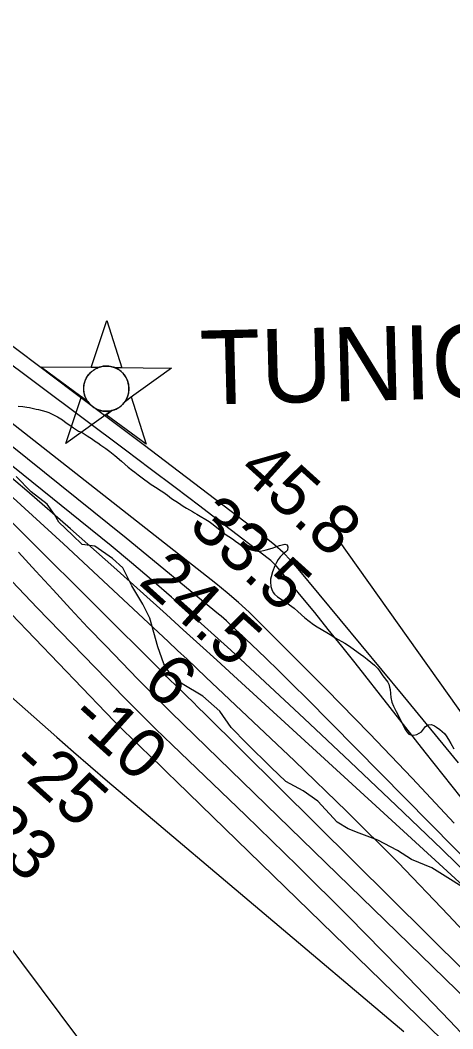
# Model space of a CAD drawing. Extents: x 3192986 to 3230865, y 867483 to 892886.
# Drawn here: x 3217089 to 3217672, y 877193 to 878555 of the extents above; entities that cross this region are included whole.
import ezdxf

# ---------------------------------------------------------------- set-up
doc = ezdxf.new("R2010")
doc.units = 0
for name, color, linetype in [('V-CHAN-NAID', 7, 'Continuous'), ('V-RIVR-EDGE', 7, 'Continuous'), ('V-RIVR-RANG', 7, 'Continuous'), ('V-SITE-VEGE', 7, 'Continuous'), ('V-TOPO-DPTH', 7, 'Continuous'), ('V-TOPO-MAJR', 7, 'Continuous'), ('V-TOPO-MINR', 7, 'Continuous'), ('V-TOPO-WATR', 7, 'Continuous')]:
    doc.layers.add(name, color=color, linetype=linetype)

msp = doc.modelspace()

# ---------------------------------------------------------------- linework, layer by layer
at = {"layer": 'V-CHAN-NAID'}
for points in [[(3217194, 878085.7), (3217184.4, 878085.8), (3217205.5, 878149.3), (3217225.8, 878085.5), (3217216.2, 878085.6), (3217214.6, 878086.1), (3217212.5, 878086.7), (3217210.5, 878087.2), (3217208.4, 878087.5), (3217207.3, 878087.6), (3217205.7, 878087.7), (3217204, 878087.7), (3217202.6, 878087.6), (3217200.7, 878087.4), (3217199.4, 878087.2), (3217197.6, 878086.8), (3217196.1, 878086.4), (3217195, 878086.1)], [(3217194, 878085.7), (3217117.5, 878086.2), (3217179.1, 878040.9), (3217178, 878042.8), (3217177.2, 878044.4), (3217176.3, 878046.4), (3217175.6, 878048.4), (3217175.3, 878049.7), (3217174.9, 878051.4), (3217174.7, 878052.8), (3217174.5, 878054.4), (3217174.4, 878056.1), (3217174.4, 878057.7), (3217174.5, 878059.8), (3217174.6, 878061.4), (3217175, 878063.6), (3217175.5, 878065.5), (3217176.1, 878067.4), (3217176.8, 878069.1), (3217177.5, 878070.7), (3217178.3, 878072.2), (3217179.4, 878074), (3217180.4, 878075.4), (3217181.4, 878076.7), (3217182.4, 878077.8), (3217183.7, 878079.2), (3217184.8, 878080.2), (3217186.5, 878081.5), (3217187.7, 878082.4), (3217189.4, 878083.5), (3217191.1, 878084.4), (3217192.6, 878085.1)], [(3217216.2, 878085.6), (3217292.7, 878085), (3217230.5, 878040.5), (3217231.4, 878042), (3217232.4, 878043.8), (3217233.1, 878045.4), (3217233.8, 878047.4), (3217234.4, 878049.1), (3217234.8, 878050.8), (3217235.1, 878052.8), (3217235.3, 878054.4), (3217235.4, 878056.6), (3217235.4, 878058.6), (3217235.2, 878060.9), (3217234.9, 878062.6), (3217234.5, 878064.8), (3217233.8, 878067), (3217233.1, 878069), (3217232.4, 878070.4), (3217231.4, 878072.3), (3217230.3, 878074.1), (3217229.1, 878075.8), (3217227.9, 878077.3), (3217226.6, 878078.7), (3217225, 878080.2), (3217223.2, 878081.6), (3217221.5, 878082.8), (3217219.7, 878083.9), (3217218.2, 878084.7)], [(3217212.4, 878027.6), (3217150.2, 877983.1), (3217171.4, 878046.5), (3217179.1, 878040.9), (3217179.7, 878039.9), (3217181.1, 878038), (3217182.3, 878036.6), (3217183.8, 878035.1), (3217185.2, 878033.9), (3217186.6, 878032.7), (3217188, 878031.7), (3217189.7, 878030.7), (3217191.4, 878029.8), (3217193.2, 878029), (3217194.7, 878028.4), (3217196.3, 878027.9), (3217198.5, 878027.3), (3217200, 878027), (3217202.1, 878026.8), (3217203.6, 878026.7), (3217205.5, 878026.6), (3217207.2, 878026.7), (3217208.9, 878026.9), (3217210.8, 878027.2)], [(3217230.5, 878040.5), (3217238.3, 878046.1), (3217258.5, 877982.3), (3217204.6, 878022), (3217212.4, 878027.6), (3217214.1, 878028.1), (3217215.7, 878028.6), (3217217.9, 878029.5), (3217219.6, 878030.4), (3217221.5, 878031.5), (3217223.2, 878032.7), (3217224.8, 878034), (3217226.1, 878035.2), (3217227.4, 878036.6), (3217228.6, 878038), (3217229.8, 878039.4)]]:
    msp.add_lwpolyline(points, close=True, dxfattribs=at)
msp.add_circle((3217204.9, 878057.2), 30.5, dxfattribs=at)
at = {"layer": 'V-RIVR-EDGE'}
msp.add_lwpolyline([(3217706.5, 877370.9), (3217644, 877410.2), (3217616.6, 877421.6), (3217597.5, 877433.8), (3217571.1, 877447.4), (3217545.9, 877457), (3217531.1, 877462.7), (3217516.3, 877471.8), (3217490.3, 877500.1), (3217470.4, 877514.1), (3217446.9, 877526.8), (3217427.4, 877545.9), (3217394.5, 877578.2), (3217373.2, 877599.5), (3217358.1, 877621.8), (3217335.1, 877641.8), (3217307.3, 877658.8), (3217293, 877669.3), (3217282.6, 877685.8), (3217274.4, 877708.5), (3217263.6, 877747.2), (3217254.1, 877766.3), (3217239.4, 877791.1), (3217227.3, 877815.5), (3217213.4, 877828.1), (3217189.5, 877844.7), (3217172.1, 877846.9), (3217159.1, 877859.6), (3217140.9, 877877), (3217134.9, 877887.5), (3217124.9, 877901.4), (3217103.6, 877918), (3217083.3, 877938.4)], dxfattribs=at)
at = {"layer": 'V-SITE-VEGE'}
for points in [[(3217086, 878033.7), (3217092.4, 878033.3), (3217097.6, 878032.3), (3217101.4, 878031.7), (3217110.3, 878029.7), (3217113.5, 878029.1), (3217118.1, 878027.9), (3217123.2, 878026.3), (3217127.2, 878024.9), (3217139, 878019.3), (3217145.5, 878015.2), (3217150.7, 878011.2), (3217157.1, 878007), (3217160.4, 878004.2), (3217167.4, 878000), (3217170.4, 877999), (3217173.4, 877997), (3217178.9, 877993.7), (3217186.1, 877988.9), (3217189.1, 877986.7), (3217193.3, 877984.1), (3217197.6, 877981.1), (3217204, 877976.6), (3217209.6, 877972.4), (3217216.3, 877967), (3217225.1, 877959.4), (3217234.2, 877951.3), (3217240, 877946.7), (3217243.2, 877944.5), (3217248, 877940.9), (3217251.2, 877938.1), (3217265.5, 877928), (3217273.4, 877923), (3217276.4, 877920.8), (3217281, 877917.8), (3217287.4, 877913.5), (3217292.9, 877909.1), (3217302.1, 877902.9), (3217308.6, 877898.5), (3217313, 877895.8), (3217321, 877891.4), (3217323.7, 877889.7), (3217327.1, 877887.9), (3217343.5, 877877.8), (3217349, 877874), (3217365.3, 877860.8), (3217375, 877854.3), (3217379.2, 877851.2), (3217388, 877845.2), (3217392.4, 877842.8), (3217398.6, 877839.9), (3217405.7, 877838.4), (3217409.4, 877837.8), (3217412.8, 877837.7), (3217416.9, 877838.5), (3217420.6, 877839.7), (3217428.5, 877841.8), (3217438.6, 877845.3), (3217445.6, 877847.4), (3217448.8, 877846.5), (3217449.8, 877843.6), (3217449.5, 877839.3), (3217447, 877836.8), (3217443.1, 877833.6), (3217439.6, 877830.2), (3217436.9, 877826.7), (3217434.4, 877822.6), (3217432, 877818), (3217428.9, 877809.7), (3217427.2, 877803.2), (3217426.4, 877799.8), (3217426.4, 877796.3), (3217426.9, 877790.3), (3217428, 877786), (3217429.8, 877782.2), (3217431.7, 877779.8), (3217435.7, 877776), (3217448.8, 877767.6), (3217458.5, 877760.8), (3217463.3, 877756.3), (3217472.8, 877747.9), (3217484.3, 877738.9), (3217489.5, 877735.5), (3217502.3, 877728.2), (3217509.3, 877723.9), (3217513.7, 877721), (3217526.6, 877713.5), (3217531.4, 877710.6), (3217534.9, 877708.3), (3217548, 877698.9), (3217552.2, 877695.5), (3217557, 877692)], [(3217557, 877692), (3217566.7, 877683.8), (3217570.8, 877679.6), (3217573.6, 877676.4), (3217578.1, 877669.5), (3217584.5, 877661), (3217585.8, 877658.2), (3217587.1, 877654.2), (3217587.8, 877650.9), (3217588.9, 877640.1), (3217590.2, 877634.1), (3217592.3, 877628.6), (3217595.8, 877621.3), (3217599, 877615.4), (3217602.2, 877608.7), (3217608.4, 877596.7), (3217610.1, 877593.8), (3217613.1, 877590.8), (3217615.9, 877589.8), (3217619.9, 877589.4), (3217623.8, 877590.3), (3217627, 877592), (3217630, 877593.9), (3217635.6, 877600.9), (3217639.2, 877603.5), (3217643.6, 877603.6), (3217647.5, 877602), (3217650.5, 877600.1), (3217654.8, 877597), (3217660.9, 877591.4), (3217663.2, 877588.5), (3217666.5, 877583.5), (3217669.6, 877578.3), (3217673.7, 877570.8)]]:
    msp.add_lwpolyline(points, dxfattribs=at)
at = {"layer": 'V-TOPO-DPTH'}
for points in [[(3217718.5, 877375.6), (3217657.3, 877435.3), (3217595.8, 877494.6), (3217533.9, 877553.4), (3217471.6, 877611.9), (3217398.9, 877679.6), (3217372.7, 877703.9), (3217346.3, 877727.9), (3217319.7, 877751.8), (3217292.9, 877775.5), (3217265.9, 877798.9), (3217238.8, 877822), (3217211.3, 877844.9), (3217183.6, 877867.5), (3216649.7, 878298.1), (3216627.4, 878315.8), (3216604.9, 878333.2), (3216582, 878350.2), (3216558.9, 878366.9), (3216314.9, 878540.4), (3216245.5, 878588.9)], [(3216228.1, 878571.6), (3216302.6, 878523.2), (3216376.3, 878473.6), (3216449.3, 878423), (3216562, 878343.6), (3216578.1, 878331.9), (3216594.1, 878320.1), (3216609.7, 878307.8), (3216625.2, 878295.4), (3216804.5, 878147.9), (3216891.8, 878074.6), (3216978.2, 878000.3), (3217063.2, 877924.4), (3217147.2, 877847.5), (3217288.3, 877715.8), (3217301.1, 877703.8), (3217313.8, 877691.8), (3217326.6, 877679.8), (3217339.3, 877667.8), (3217458.7, 877554.6), (3217529.2, 877486.4), (3217598.6, 877417.2), (3217666.5, 877346.5), (3217733.3, 877274.7)], [(3216228.1, 878571.6), (3216302.6, 878523.2), (3216376.3, 878473.6), (3216449.3, 878423), (3216562, 878343.6), (3216578.1, 878331.9), (3216594.1, 878320.1), (3216609.7, 878307.8), (3216625.2, 878295.4), (3216804.5, 878147.9), (3216891.8, 878074.6), (3216978.2, 878000.3), (3217063.2, 877924.4), (3217147.2, 877847.5), (3217288.3, 877715.8), (3217301.1, 877703.8), (3217313.8, 877691.8), (3217326.6, 877679.8), (3217339.3, 877667.8), (3217458.7, 877554.6), (3217529.2, 877486.4), (3217598.6, 877417.2), (3217666.5, 877346.5), (3217733.3, 877274.7)], [(3217086.3, 877836.5), (3217109.6, 877811), (3217132.9, 877785.4), (3217156.4, 877760), (3217180.1, 877734.9), (3217204.1, 877709.9), (3217247.5, 877665.1), (3217258.5, 877653.8), (3217269.6, 877642.6), (3217280.7, 877631.5), (3217292, 877620.5), (3217709.7, 877214)], [(3217709.7, 877214), (3217292, 877620.5), (3217280.7, 877631.5), (3217269.6, 877642.6), (3217258.5, 877653.8), (3217247.5, 877665.1), (3217204.1, 877709.9), (3217180.1, 877734.9), (3217156.4, 877760), (3217132.9, 877785.4), (3217109.6, 877811), (3217086.3, 877836.5)], [(3217771.9, 877067.3), (3217299.6, 877527), (3217287.6, 877538.6), (3217275.7, 877550.1), (3217263.7, 877561.6), (3217251.6, 877573), (3217239.6, 877584.5), (3217227.7, 877596.1), (3217216, 877607.9), (3217204.4, 877619.8), (3217012.3, 877819.9)], [(3217771.9, 877067.3), (3217299.6, 877527), (3217287.6, 877538.6), (3217275.7, 877550.1), (3217263.7, 877561.6), (3217251.6, 877573), (3217239.6, 877584.5), (3217227.7, 877596.1), (3217216, 877607.9), (3217204.4, 877619.8), (3217012.3, 877819.9)], [(3216912.6, 877785.8), (3217137.9, 877586.6), (3217160.6, 877566.7), (3217183.4, 877546.9), (3217206.3, 877527.2), (3217229.3, 877507.7), (3217606.1, 877189.4)], [(3216912.6, 877785.8), (3217137.9, 877586.6), (3217160.6, 877566.7), (3217183.4, 877546.9), (3217206.3, 877527.2), (3217229.3, 877507.7), (3217606.1, 877189.4)], [(3217167.7, 877179.3), (3217040.1, 877350)], [(3217167.7, 877179.3), (3217040.1, 877350)]]:
    msp.add_lwpolyline(points, dxfattribs=at)
at = {"layer": 'V-TOPO-MAJR'}
msp.add_lwpolyline([(3217683.7, 877505), (3217635, 877566.6), (3217540.4, 877686.9), (3217522.4, 877709.6), (3217504.3, 877732.2), (3217486, 877754.8), (3217467.7, 877777.2), (3217437.3, 877814.3), (3217434, 877818), (3217430.5, 877821.6), (3217426.8, 877825), (3217423, 877828.1), (3217364.4, 877873), (3217331, 877898.4), (3217297.7, 877923.7), (3217264.2, 877949), (3217230.7, 877974.1), (3216705.5, 878366.9), (3216683.2, 878384.2), (3216661.2, 878402), (3216639.9, 878420.5), (3216619, 878439.5), (3216440, 878607.1)], dxfattribs=at)
at = {"layer": 'V-TOPO-MINR'}
for points in [[(3217674.3, 877470.5), (3217617.5, 877531.5), (3217559.7, 877591.7), (3217501.4, 877651.3), (3217411.7, 877741.6), (3217397.5, 877755.3), (3217383, 877768.7), (3217368, 877781.6), (3217352.7, 877794.1), (3216777, 878246.3), (3216752.2, 878265.5), (3216727.1, 878284.5), (3216701.9, 878303.2), (3216676.4, 878321.6), (3216650.8, 878339.8), (3216625.1, 878357.9), (3216599.3, 878375.9), (3216573.4, 878393.7), (3216102.7, 878717.2)], [(3217907.9, 877200.2), (3217474.8, 877639.1), (3217456.6, 877657.4), (3217438.2, 877675.6), (3217419.7, 877693.6), (3217401, 877711.5), (3217370.2, 877740.7), (3217366.8, 877743.9), (3217363.4, 877747), (3217359.9, 877750), (3217356.4, 877752.9), (3217231.4, 877855.2), (3217165.2, 877909.1), (3217098.7, 877962.5), (3217031.8, 878015.5), (3216964.6, 878068.1), (3216665.3, 878300.6), (3216638.6, 878321.2), (3216611.6, 878341.4), (3216584.4, 878361.4), (3216557, 878381.1), (3216210.8, 878626.6)], [(3217718.5, 877375.6), (3217657.3, 877435.3), (3217595.8, 877494.6), (3217533.9, 877553.4), (3217471.6, 877611.9), (3217398.9, 877679.6), (3217372.7, 877703.9), (3217346.3, 877727.9), (3217319.7, 877751.8), (3217292.9, 877775.5), (3217265.9, 877798.9), (3217238.8, 877822), (3217211.3, 877844.9), (3217183.6, 877867.5), (3216649.7, 878298.1), (3216627.4, 878315.8), (3216604.9, 878333.2), (3216582, 878350.2), (3216558.9, 878366.9), (3216314.9, 878540.4), (3216245.5, 878588.9)], [(3217824.6, 877258.9), (3217376.3, 877670), (3217353.8, 877690.6), (3217331.2, 877711.2), (3217308.6, 877731.7), (3217285.9, 877752.1), (3217215, 877816), (3217156.5, 877867.9), (3217097.4, 877919.2), (3217037.7, 877969.6), (3216977.4, 878019.5), (3216637.5, 878296.7), (3216618.6, 878311.8), (3216599.4, 878326.6), (3216580, 878341.1), (3216560.4, 878355.3), (3216415.4, 878458), (3216328, 878518.7), (3216240, 878578.5)], [(3217679.9, 877552.1), (3217642.7, 877597.6), (3217605.4, 877643), (3217463.9, 877813.8), (3217453.9, 877825.1), (3217443.3, 877835.9), (3217432.1, 877845.9), (3217420.3, 877855.5), (3217254.4, 877981.6), (3217159.2, 878053.6), (3217063.9, 878125.4), (3216968.3, 878197), (3216872.5, 878268.3), (3216702.2, 878394.7), (3216687.8, 878405.8), (3216673.7, 878417.2), (3216659.9, 878429.1), (3216646.4, 878441.3), (3216536.9, 878543.8), (3216511.9, 878568.6)], [(3217840.3, 877119.9), (3217337.1, 877618.6), (3217329.3, 877626.4), (3217321.4, 877634.2), (3217313.5, 877641.9), (3217305.6, 877649.6), (3217290.5, 877664.2), (3217289.3, 877665.4), (3217286.5, 877668.3), (3217283.6, 877671.4), (3217281.7, 877673.4), (3217280.7, 877674.4), (3217279.7, 877675.4), (3217010.7, 877942.7)], [(3217840.8, 877398.3), (3217518.1, 877853.3)], [(3217709.7, 877214), (3217292, 877620.5), (3217280.7, 877631.5), (3217269.6, 877642.6), (3217258.5, 877653.8), (3217247.5, 877665.1), (3217204.1, 877709.9), (3217180.1, 877734.9), (3217156.4, 877760), (3217132.9, 877785.4), (3217109.6, 877811), (3217086.3, 877836.5)], [(3217771.9, 877067.3), (3217299.6, 877527), (3217287.6, 877538.6), (3217275.7, 877550.1), (3217263.7, 877561.6), (3217251.6, 877573), (3217239.6, 877584.5), (3217227.7, 877596.1), (3217216, 877607.9), (3217204.4, 877619.8), (3217012.3, 877819.9)], [(3217772.6, 877093.1), (3217668.2, 877203.6), (3217600.5, 877274.2), (3217532.1, 877344.1), (3217462.7, 877413.1), (3217392.7, 877481.3), (3217293.7, 877576.3), (3217271.4, 877598), (3217249.2, 877619.9), (3217227.2, 877642.1), (3217205.4, 877664.4), (3217111.7, 877761.5), (3217069.3, 877806)], [(3216912.6, 877785.8), (3217137.9, 877586.6), (3217160.6, 877566.7), (3217183.4, 877546.9), (3217206.3, 877527.2), (3217229.3, 877507.7), (3217606.1, 877189.4)], [(3217167.7, 877179.3), (3217040.1, 877350)]]:
    msp.add_lwpolyline(points, dxfattribs=at)
at = {"layer": 'V-TOPO-WATR'}
msp.add_lwpolyline([(3217733.3, 877274.7), (3217666.5, 877346.5), (3217598.6, 877417.2), (3217529.2, 877486.4), (3217458.7, 877554.6), (3217339.3, 877667.8), (3217326.6, 877679.8), (3217313.8, 877691.8), (3217301.1, 877703.8), (3217288.3, 877715.8), (3217147.2, 877847.5), (3217063.2, 877924.4), (3216978.2, 878000.3), (3216891.8, 878074.6), (3216804.5, 878147.9), (3216625.2, 878295.4), (3216609.7, 878307.8), (3216594.1, 878320.1), (3216578.1, 878331.9), (3216562, 878343.6), (3216449.3, 878423), (3216376.3, 878473.6), (3216302.6, 878523.2), (3216228.1, 878571.6)], dxfattribs=at)

# ---------------------------------------------------------------- texts
at = {"layer": 'V-CHAN-NAID'}
msp.add_text('TUNICA BLUFF (292.2)', height=100, rotation=1.4048, dxfattribs=at).set_placement((3217332.5, 878035.5))
at = {"layer": 'V-RIVR-RANG'}
for s, rotation, p in [('45.8', 317.8783, (3217380.6, 877943.7)), ('33.5', 317.8783, (3217313.7, 877869.3)), ('24.5', 318.0233, (3217246.7, 877794.7)), ('6', 318.0233, (3217251, 877656.3)), ('-10', 318.0233, (3217152.5, 877610.4)), ('-25', 318.0233, (3217072.5, 877547.9)), ('-23', 318.0233, (3217004.5, 877474.6))]:
    msp.add_text(s, height=67, rotation=rotation, dxfattribs=at).set_placement(p)

doc.saveas('drawing.dxf')
